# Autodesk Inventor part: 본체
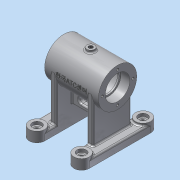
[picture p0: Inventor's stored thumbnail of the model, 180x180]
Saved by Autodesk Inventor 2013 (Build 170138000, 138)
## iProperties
Created: 2015-11
Part Number: 본체
Material: 알루미늄 6061
Document SubType Name: Modeling
Designer: User11
Density: 2.71 g/cm^3
Mass: 357.638 g
Surface Area: 467.122 cm^2
Volume: 131.97 cm^3
Author: User11
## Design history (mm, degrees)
sketch "스케치2"
  geometry: L1 (0, 0)-(70, 0); L2 (0, 25)-(70, 25); L3 (70, 25)-(70, 16); L4 (70, 16)-(58, 16); L5 (58, 16)-(58, 14); L6 (58, 14)-(56, 14); L7 (56, 14)-(56, 21); L8 (56, 21)-(14, 21); L9 (14, 21)-(14, 14); L10 (14, 14)-(12, 14); L11 (12, 14)-(12, 16); L12 (12, 16)-(0, 16); L13 (0, 16)-(0, 25)
  constraints: 26 end point, 6 parallel, 6 perpendicular, 1 horizontal
  dimensions: "d0" = 70 distance of L1.start L1.end; "d1" = 0 distance from line of L13 L1.start; "d2" = 70 distance between parallel lines of L13 L3; "d3" = 42 diameter of L8 L1; "d4" = 50 diameter of L2 L1; "d5" = 32 diameter of L4 L1; "d7" = 28 diameter of L6 L1; "d9" = 28 diameter of L10 L1; "d10" = 32 diameter of L12 L1; "d11" = 12 distance of L3.end L4.end; "d12" = 12 distance of L11.end L12.end; "d13" = 2 distance of L5.end L6.end; "d14" = 2 distance of L9.end L10.end
revolve "회전1" sketch "스케치2" stored, may be unused: angle "d15" = 90 deg
fillet "모깎기1" dims "d16" = 0.3
sketch "스케치3"
  geometry: L1 (0, 0)-(0, 20); L2 (0, 0)-(0, -20); L3 (0, 0)-(-20, 0); L4 (0, 0)-(20, 0); C1 r 25 at (0, 0) reference; A1 r 20 centre (0, 0) between (0, 20) and (0, -20); 4 further points
  constraints: 8 end point, 5 coincident, 4 point on circle, 2 collinear, 1 centre point, 1 perpendicular, 1 vertical
  dimensions: "d17" = 40 diameter of A1
hole "구멍1" sketch "스케치3" at (0, -20), (-20, 0), (0, 20), (20, 0) diameter "d19" = 3.242; stored, may be unused: countersink angle "d23" = 90 deg, drill point angle "d25" = 118 deg; dims "d20" = 8, "d21" = 4, "d22" = 2, "d24" = 10
sketch "스케치4"
  geometry: C1 r 16 at (0, 0) reference; C2 r 20 at (0, 0); C3 r 21 at (0, 0) reference; C4 r 1.621 at (0, 20) reference; C5 r 1.621 at (-20, 0) reference; C6 r 1.621 at (0, -20) reference; C7 r 1.621 at (20, 0) reference; 4 further points
  constraints: 5 coincident, 1 centre point
  dimensions: "d26" = 40 diameter of C2
hole "구멍2" sketch "스케치4" at (20, 0), (0, -20), (-20, 0), (0, 20) diameter "d28" = 3.242; stored, may be unused: countersink angle "d32" = 90 deg, drill point angle "d34" = 118 deg; dims "d29" = 8, "d30" = 4, "d31" = 2, "d33" = 10
fillet "모깎기2" dims "d35" = 3
node "작업 평면1"
sketch "스케치5"
  geometry: L1 (70, -25)-(70, 25) reference; L2 (0, -25)-(0, 25) reference; L3 (70, 0)-(0, 0); L4 (0, 25)-(70, 25) reference; L5 (35, 25)-(35, 0); C1 r 5 at (35, 0)
  constraints: 4 end point, 3 midpoint, 1 centre point, 1 coincident, 1 perpendicular
  dimensions: "d37" = 10 diameter of C1
extrude "돌출1" join sketch "스케치5" stored distance "d39" = 10; taper "d40" = 0 deg
sketch "스케치6"
  geometry: C1 r 5 at (0, 0) reference; 1 further point
hole "구멍3" sketch "스케치6" at (0, 0) diameter "d41" = 5.188; stored, may be unused: countersink angle "d45" = 90 deg, drill point angle "d47" = 118 deg; dims "d42" = 8, "d43" = 4, "d44" = 2, "d46" = 10
node "작업 평면6"
sketch "스케치7"
  geometry: L1 (55, -41.857)-(55, 38.143); L2 (75, -41.857)-(75, 38.143); L3 (65, -41.857)-(55, -41.857); L4 (65, 38.143)-(55, 38.143); L5 (0, -25)-(0, 25) reference; L6 (0, -25)-(0, 25) reference; L7 (70, -25)-(70, 25) reference; L8 (55, -1.857)-(75, -1.857); L9 (35, 5)-(35, -5); A1 r 10 centre (65, -41.857) between (55, -41.857) and (75, -41.857); A2 r 10 centre (65, 38.143) between (75, 38.143) and (55, 38.143); A3 r 10 centre (65, 38.143) between (55, 38.143) and (75, 38.143); A4 r 10 centre (65, -41.857) between (75, -41.857) and (55, -41.857); 1 further point
  constraints: 12 end point, 8 point on circle, 5 tangent, 4 centre point, 2 midpoint, 2 parallel, 2 perpendicular, 1 vertical, 1 vertical alignment, 1 other
  dimensions: "d53" = 20 diameter of A1; "d55" = 20 diameter of A2; "d56" = 80 distance between parallel lines of L4 L3; "d58" = 30 distance from line of L3.start L9
  node "투영된 루프2"
extrude "돌출2" join sketch "스케치7" distance "d59" = 13; taper "d60" = 0 deg
extrude "돌출3" join sketch "스케치7" distance "d61" = 10; taper "d62" = 0 deg
sketch "스케치8"
  geometry: C1 r 10 at (0, 0) reference; C2 r 6 at (0, 0); 1 further point
  constraints: 1 centre point, 1 coincident
  dimensions: "d63" = 12 diameter of C2
sketch "스케치9"
  geometry: C1 r 10 at (0, 0) reference; C2 r 6 at (0, 0); 1 further point
  constraints: 1 centre point, 1 coincident
  dimensions: "d65" = 12 diameter of C2
extrude "돌출4" cut sketch "스케치8" distance "d67" = 4; taper "d68" = 0 deg
extrude "돌출5" cut sketch "스케치9" distance "d69" = 4; taper "d70" = 0 deg
sketch "스케치10"
  geometry: C1 r 6 at (0, 0) reference; C2 r 3 at (0, 0); 1 further point
  constraints: 1 centre point, 1 coincident
  dimensions: "d71" = 6 diameter of C2
sketch "스케치11"
  geometry: C1 r 6 at (0, 0) reference; C2 r 3 at (0, 0); 1 further point
  constraints: 1 centre point, 1 coincident
  dimensions: "d73" = 6 diameter of C2
extrude "돌출6" cut sketch "스케치10" stored distance "d75" = 4; taper "d76" = 0 deg
extrude "돌출7" cut sketch "스케치11" stored distance "d77" = 4; taper "d78" = 0 deg
fillet "모깎기3" dims "d79" = 0.3
chamfer "모따기1" distance "d80" = 1; stored, may be unused: second distance "d81" = 2, angle "d82" = 45 deg
chamfer "모따기2" distance "d83" = 1; stored, may be unused: second distance "d84" = 2, angle "d85" = 45 deg
sketch "스케치12"
  geometry: L1 (55, 38.143)-(55, -41.857) reference; L2 (55, -25)-(63, -25); L3 (63, -25)-(63, 25); L4 (63, 25)-(55, 25); 1 further point
  constraints: 6 end point, 3 perpendicular, 2 point on line
  dimensions: "d86" = 50 distance of L2.end L3.end; "d88" = 8 distance between parallel lines of L1 L3; "d89" = 25 distance from line of L2 point (0, 0)
extrude "돌출9" join sketch "스케치12" stored distance "d92" = 4; taper "d93" = 0 deg
node "작업 평면7"
sketch "스케치14"
  geometry: L1 (-5, 40)-(-5, -40); L2 (15, 40)-(15, -40); L3 (5, 40)-(5, -40); L4 (5, 40)-(15, 40); L5 (15, 0)-(-5, 0); C1 r 5 at (35, 0) reference; A1 r 10 centre (5, 40) between (-5, 40) and (15, 40); A2 r 10 centre (5, -40) between (-5, -40) and (15, -40); 1 further point
  constraints: 10 end point, 4 point on circle, 3 tangent, 2 centre point, 2 midpoint, 1 parallel, 1 perpendicular, 1 vertical
  dimensions: "d95" = 20 diameter of A1; "d97" = 20 diameter of A2; "d98" = 80 distance of L3.start L3.end; "d99" = 40 distance from line of L4 point (0, 0); "d100" = 30 distance from line of L3 C1.centre
extrude "돌출10" join sketch "스케치14" distance "d101" = 13; taper "d102" = 0 deg
extrude "돌출11" join sketch "스케치14" distance "d103" = 10; taper "d104" = 0 deg
sketch "스케치15"
  geometry: C1 r 10 at (0, 0) reference; C2 r 6 at (0, 0); 1 further point
  constraints: 1 centre point, 1 coincident
  dimensions: "d105" = 12 diameter of C2
sketch "스케치16"
  geometry: C1 r 10 at (0, 0) reference; C2 r 6 at (0, 0); 1 further point
  constraints: 1 centre point, 1 coincident
  dimensions: "d107" = 12 diameter of C2
extrude "돌출12" cut sketch "스케치15" distance "d109" = 4; taper "d110" = 0 deg
extrude "돌출13" cut sketch "스케치16" distance "d111" = 4; taper "d112" = 0 deg
sketch "스케치17"
  geometry: C1 r 6 at (0, 0) reference; C2 r 3 at (0, 0); 1 further point
  constraints: 1 centre point, 1 coincident
  dimensions: "d113" = 6 diameter of C2
sketch "스케치18"
  geometry: C1 r 6 at (0, 0) reference; C2 r 3 at (0, 0); 1 further point
  constraints: 1 centre point, 1 coincident
  dimensions: "d115" = 6 diameter of C2
extrude "돌출14" cut sketch "스케치17" stored distance "d117" = 4; taper "d118" = 0 deg
extrude "돌출15" cut sketch "스케치18" stored distance "d119" = 4; taper "d120" = 0 deg
chamfer "모따기3" distance "d121" = 1; stored, may be unused: second distance "d122" = 2, angle "d123" = 45 deg
chamfer "모따기4" distance "d124" = 1; stored, may be unused: second distance "d125" = 2, angle "d126" = 45 deg
sketch "스케치19"
  geometry: L1 (15, -40)-(15, 40) reference; L2 (15, 25)-(7, 25); L3 (7, 25)-(7, -25); L4 (7, -25)-(15, -25); 1 further point
  constraints: 6 end point, 2 perpendicular, 2 point on line, 1 parallel
  dimensions: "d127" = 8 distance of L2.start L2.end; "d129" = 25 distance from line of point (0, 0) L2; "d130" = 50 distance of L2.end L3.end
extrude "돌출16" join sketch "스케치19" stored distance "d131" = 4; taper "d132" = 0 deg
fillet "모깎기4" dims "d133" = 2
fillet "모깎기5" dims "d134" = 2
sketch "스케치20"
  geometry: L1 (-15, -60)-(-15, -9.798) reference; L2 (0, -25)-(-70, -25) reference; L3 (-55, -60)-(-55, -9.798) reference; L4 (-15, -45)-(-55, -45); L5 (-55, -45)-(-55, -25); L6 (-55, -25)-(-15, -25); L7 (-15, -25)-(-15, -45); L8 (-27, -31.5)-(-43, -31.5); L9 (-43, -38.5)-(-27, -38.5); L10 (-23.5, -35)-(-46.5, -35); L11 (-35, -45)-(-35, -25); L12 (5, -68)-(-15, -68) reference; A1 r 3.5 centre (-43, -35) between (-43, -31.5) and (-43, -38.5); A2 r 3.5 centre (-27, -35) between (-27, -38.5) and (-27, -31.5); 1 further point
  constraints: 16 end point, 6 point on circle, 3 parallel, 3 point on line, 3 tangent, 2 centre point, 2 midpoint, 2 perpendicular, 1 horizontal
  dimensions: "d135" = 20 distance of L6.end L4.start; "d138" = 23 distance of L10.start L10.end; "d139" = 3.5 radius of A1; "d140" = 11.5 distance from line of L10.start L11; "d141" = 33 distance between parallel lines of L12 L10
extrude "돌출17" join sketch "스케치20" stored distance "d142" = 8; taper "d143" = 0 deg
fillet "모깎기6" dims "d144" = 2
fillet "모깎기7" dims "d145" = 2
node "작업 평면8"
sketch "스케치21"
  geometry: L1 (21.079, 1.97)-(48.921, 1.97); L2 (48.921, 1.97)-(48.921, -1.97); L3 (48.921, -1.97)-(21.079, -1.97); L4 (21.079, -1.97)-(21.079, 1.97); L5 (21.079, 0)-(48.921, 0); L6 (35, 1.97)-(35, -1.97); L7 (0, -25)-(0, 25) reference; L8 (0, 25)-(70, 25) reference; 1 further point
  constraints: 4 end point, 4 midpoint, 1 parallel, 2 other
  dimensions: "d147" = 35 distance between parallel lines of L7 L6; "d149" = 25 distance between parallel lines of L5 L8
feature "엠보싱1" sketch "스케치21" dims "d16" = 0.3, "d150" = 0.5, "d151" = 0
fillet "모깎기8" dims "d152" = 2
node "솔리드1"
node "투영된 루프1"
other parameters: "d36" = 28, "d52" = -68, "d94" = -68, "d146" = -83.75
